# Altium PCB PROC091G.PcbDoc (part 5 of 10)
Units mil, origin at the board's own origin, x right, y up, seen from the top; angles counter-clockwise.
Board outline 4538.11 x 994.94 mil, 8 copper layers (Top Layer, GND1, Sig1, PWR1, PWR2, Sig2, GND2, Bottom Layer), stack 59.155 mil thick; 446 components, 329 nets, 5050 pads, 868 vias.
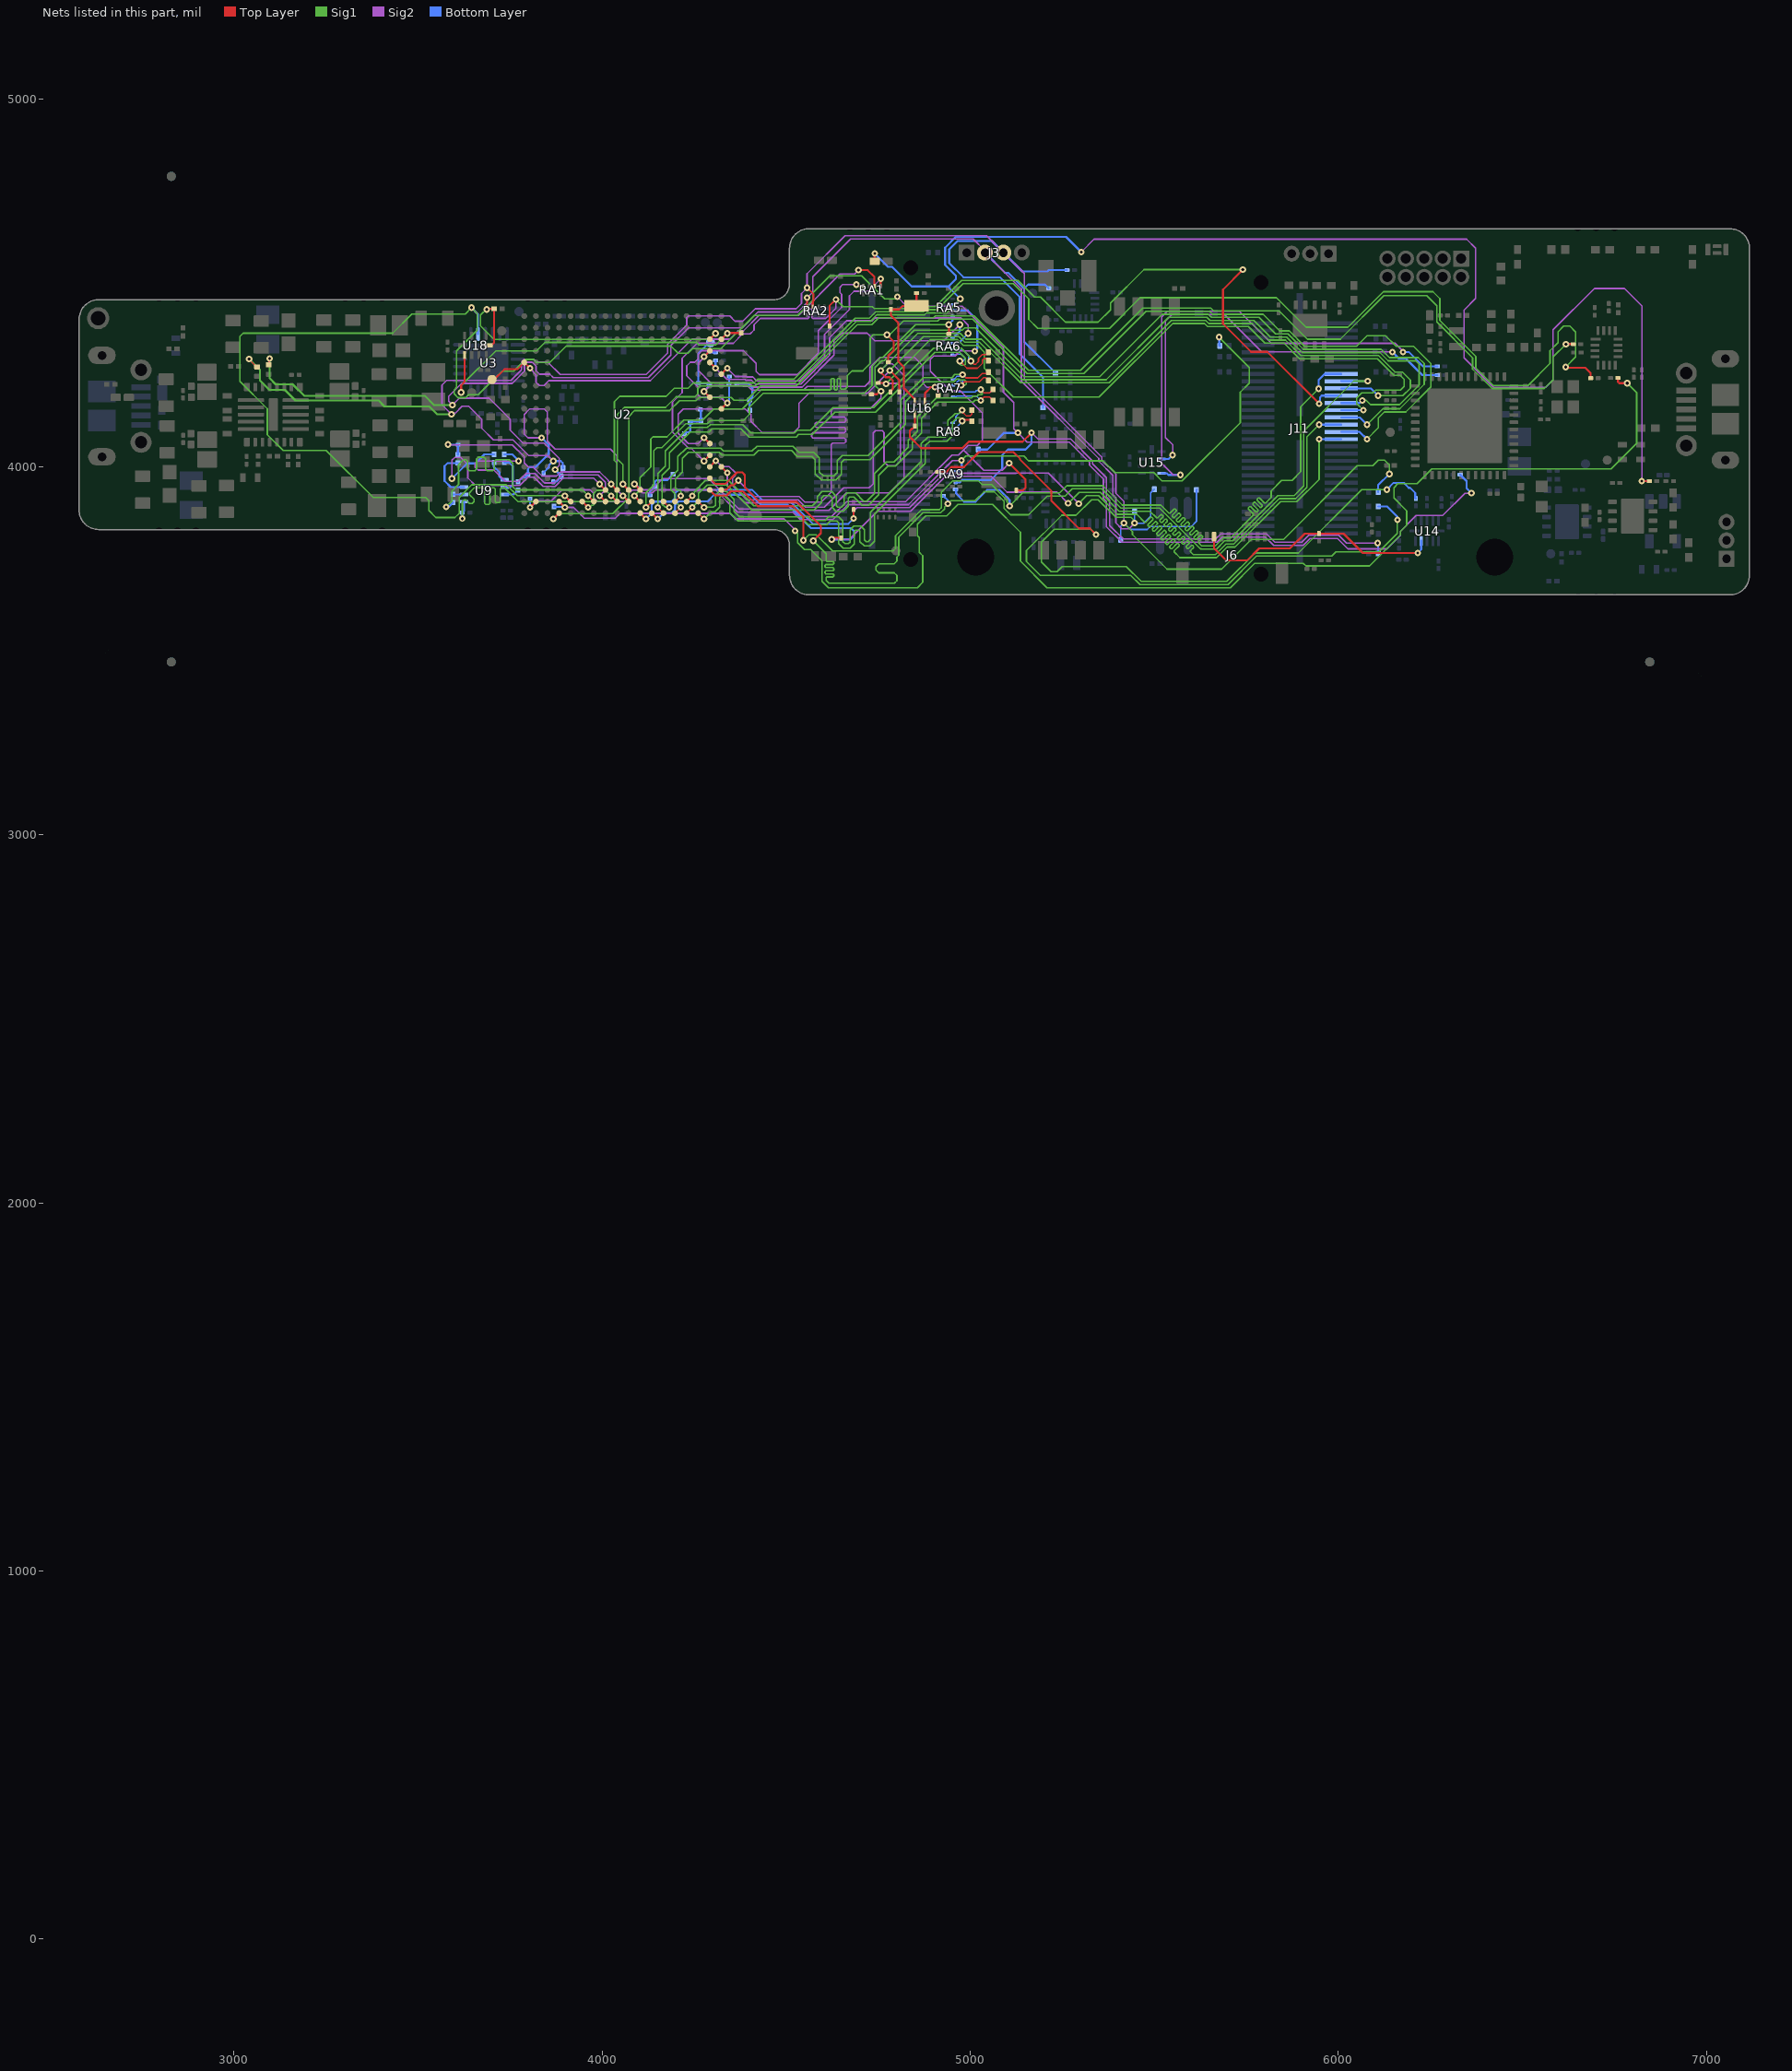
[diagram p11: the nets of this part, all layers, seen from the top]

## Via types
v1: diameter 18, hole 8, Top Layer to Bottom Layer, tented both sides, 832 vias
v2: diameter 19.68, hole 7.87, Top Layer to Bottom Layer, tented both sides, 34 vias
v3: diameter 17, hole 7.87, Top Layer to Bottom Layer, tented both sides, 1 vias
v4: diameter 17, hole 8, Top Layer to Bottom Layer, tented both sides, 1 vias

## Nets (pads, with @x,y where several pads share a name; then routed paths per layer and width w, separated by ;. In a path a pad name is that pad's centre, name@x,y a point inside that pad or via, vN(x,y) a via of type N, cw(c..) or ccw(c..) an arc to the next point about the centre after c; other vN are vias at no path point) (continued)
AR_CS1_LCD: R76.2 R106.2 | length 1971.8
  Top Layer w5.5: R106.2@4912.37,3985.56 4935.15,3985.56 4948.84,3999.25 4983.35,3999.25 5023.93,4039.83 5117.4,4039.83 5135.68,4021.55 5135.68,4019.4 5220.75,3934.33 5220.75,3907 5295.27,3832.48 5325.11,3832.48 v1(5341.82,3815.77)
  Sig1 w4.2: v1(5341.82,3815.77) 5327.56,3830.03 5228.54,3830.03 5193.48,3794.98 5193.48,3741.37 5219.62,3715.24 5236.36,3715.24 5250.14,3729.01 5423.81,3729.01 5464.6,3688.21 5696.86,3688.21 5774.21,3765.56 5891.75,3765.56 6064.18,3938 v1(6132,3938)
  Bottom Layer w5.5: v1(6132,3938) 6150.21,3956.21 6178.19,3956.21 6191.57,3942.84 6194.98,3942.84 6209.15,3928.68 6209.15,3915.09 R76.2@6210.78,3913.46
AR_CS1_LCD_T: J6.3 R183.1 U14.4 | length 688.3
  Top Layer w5.5: J6.3@5662.69,3810.06 5662.69,3778.74 5696.19,3745.25 5752.29,3745.25 5785.06,3778.01 5868.52,3778.01 5908.94,3818.43 R183.1@5947.68,3818.43 6014.38,3818.43 6067,3765.81 v1(6215.84,3765.81)
  Bottom Layer w5.5: v1(6215.84,3765.81) 6225.29,3775.26 U14.4@6225.29,3797.8 U14.4@6225.29,3799.77
AR_DMM_CLK: J11.15 R11.1 U2.U3 | length 2987.9
  Top Layer w5.5: U2.U3@4292.7,3936.89 4307.32,3922.26 4338.99,3922.26 4350.2,3933.47 4382.53,3933.47 4423.2,3892.8 4518.93,3892.8 4546.57,3865.15 v1(4546.57,3799.81)
  Sig1 w4.2: v1(4546.57,3799.81) 4562.05,3815.29 4582.04,3815.29 4626.12,3771.22 4790.64,3771.22 4797.35,3777.92 4797.35,3812.59 4868.02,3883.26 4916.38,3883.26 4922.15,3889.03 4922.15,3931.08 4952.52,3961.45 5022.73,3961.45 5032.58,3951.6 5057.93,3951.6 5100.15,3909.38 5100.15,3904.15 5107.05,3897.25 v1(5107.05,3893.52) 5142.43,3928.9 5242.97,3928.9 5262.41,3948.34 5360.74,3948.34 5413.2,3895.88 5518.19,3895.88 5539.96,3874.11 5542.93,3874.11 5553.82,3885 5556.79,3885 5559.76,3882.03 5559.76,3879.06 5548.87,3868.17 5548.87,3865.2 5551.84,3862.23 5554.81,3862.23 5565.7,3873.12 5568.67,3873.12 5571.64,3870.15 5571.64,3867.18 5560.75,3856.29 5560.75,3853.32 5563.72,3850.35 5566.69,3850.35 5577.58,3861.24 5580.55,3861.24 5583.52,3858.27 5583.52,3855.3 5572.62,3844.41 5572.62,3841.44 5575.59,3838.47 5578.56,3838.47 5589.46,3849.37 5592.43,3849.37 5595.4,3846.4 5595.4,3843.43 5584.5,3832.53 5584.5,3829.56 5587.47,3826.59 5590.44,3826.59 5601.34,3837.49 5604.31,3837.49 5607.27,3834.52 5607.27,3831.55 5596.38,3820.65 5596.38,3817.69 5599.35,3814.72 5602.32,3814.72 5613.21,3825.61 5616.18,3825.61 5619.15,3822.64 5619.15,3819.67 5608.26,3808.78 5608.26,3805.81 5611.23,3802.84 5614.2,3802.84 5625.2,3813.84 5628.17,3813.84 5631.14,3810.87 5631.14,3807.9 5620.14,3796.9 5620.14,3793.93 5628.77,3785.3 5666.23,3785.3 5687.95,3807.02 5708.3,3807.02 5769.88,3868.6 5769.88,3871.57 5756.13,3885.32 5756.13,3888.29 5759.1,3891.26 5762.07,3891.26 5775.82,3877.51 5778.79,3877.51 5781.76,3880.48 5781.76,3883.45 5768.01,3897.2 5768.01,3900.17 5770.98,3903.14 5773.95,3903.14 5787.7,3889.39 5790.67,3889.39 5793.64,3892.36 5793.64,3895.33 5779.89,3909.08 5779.89,3912.05 5782.86,3915.02 5785.83,3915.02 5799.58,3901.27 5802.55,3901.27 5817.91,3916.63 5817.91,3934.39 5846.28,3962.76 5874.33,3962.76 5897.85,3986.27 5897.85,4163.26 v1(5946.67,4212.08)
  Bottom Layer w5.5: R11.1@4960.02,3937.94 4961.69,3937.94 4961.69,3926.94 4983.21,3905.42 5014.32,3905.42 5045.7,3936.8 5080.2,3936.8 5107.05,3909.95 v1(5107.05,3893.52) ; v1(5946.67,4212.08) 5946.67,4235.89 5962.91,4252.14 J11.15@6007.91,4252.14
AR_DMM_SYNC: J11.17 R10.1 U2.U4 | length 2944.6
  Top Layer w5.5: U2.U4@4292.7,3968.38 4307.32,3953.76 4335.57,3953.76 4366.31,3984.5 4380.6,3984.5 4388,3977.1 4388,3944.27 4427.07,3905.2 4528.29,3905.2 4594.49,3839 4594.49,3819.69 v1(4573.55,3798.74)
  Sig1 w4.2: v1(4573.55,3798.74) 4608.7,3763.59 4608.7,3745.54 4611.65,3742.59 4627.33,3742.59 4629.43,3740.49 4629.43,3736.29 4627.33,3734.19 4607.72,3734.19 4605.62,3732.09 4605.62,3727.89 4607.72,3725.79 4627.33,3725.79 4629.43,3723.69 4629.43,3719.49 4627.33,3717.39 4607.72,3717.39 4605.62,3715.29 4605.62,3711.09 4607.72,3708.99 4627.33,3708.99 4629.43,3706.89 4629.43,3702.69 4627.33,3700.59 4610.8,3700.59 4608.7,3698.49 4608.7,3690.96 4616.3,3683.36 4793.88,3683.36 4800.87,3690.35 4800.87,3704.68 4793.61,3711.94 4751.42,3711.94 4744.16,3719.2 4744.16,3728.88 4751.42,3736.14 4793.61,3736.14 4800.87,3743.4 4800.87,3754.27 4806.18,3759.58 4806.18,3808.91 4872.14,3874.86 4919.86,3874.86 4930.55,3885.55 4930.55,3890.83 v1(4939.38,3899.66) 4947.59,3907.87 5013.3,3907.87 5037.73,3932.3 5065.35,3932.3 5091.75,3905.9 5091.75,3887.18 5109.3,3869.63 5158.29,3869.63 5209.16,3920.5 5258.24,3920.5 5277.67,3939.94 5357.26,3939.94 5409.72,3887.48 5514.71,3887.48 5625.29,3776.9 5627.71,3776.9 5627.97,3776.64 5669.45,3776.64 5691.43,3798.62 5712.88,3798.62 5836.14,3921.88 5880.54,3921.88 5906.25,3947.58 5906.25,4096.8 6041.9,4232.45 v1(6080,4232.45)
  Bottom Layer w5.5: R10.1@4927.02,3921 4939.38,3908.65 v1(4939.38,3899.66) ; J11.17@6007.91,4232.45 v1(6080,4232.45)
AR_DP0: J11.19 R88.1 U2.U7 | length 2828.1
  Top Layer w5.5: v1(4276.95,4078.62) U2.U7@4292.7,4062.87 ; v1(4781.5,4261.73) 4807.4,4235.84 R88.1@4807.4,4202.68
  Sig1 w4.2: v1(4781.5,4261.73) 4873.42,4353.65 4969.55,4353.65 4984.88,4338.32 5025.32,4338.32 5047.08,4316.55 5048.98,4316.55 5137.45,4228.08 5377.24,4228.08 5546.66,4397.5 5639.88,4397.5 5648.28,4389.1 5766.35,4389.1 5811.43,4344.02 5856.43,4344.02 5898.4,4302.05 6109.66,4302.05 6154.56,4257.15 6174.68,4257.15 6195.7,4236.13 6195.7,4213.63 6175.16,4193.08 v1(6108.22,4193.08)
  Sig2 w4.2: v1(4276.95,4078.62) 4261.23,4062.89 4234.4,4062.89 4207.08,4090.21 4207.08,4100.94 4207.08,4111.59 4207.08,4143.33 4220.78,4157.04 4389.09,4157.04 4404.46,4141.67 4404.46,4123.28 4435.52,4092.22 4519.97,4092.22 4535.14,4107.38 4535.14,4172.74 4551.69,4189.3 4551.95,4189.3 4562.68,4200.02 4721.12,4200.02 4781.5,4260.41 v1(4781.5,4261.73)
  Bottom Layer w5.5: J11.19@6007.91,4212.77 6088.54,4212.77 v1(6108.22,4193.08)
AR_DP1: J11.21 R130.1 U2.U6 | length 2845.6
  Top Layer w5.5: v1(4276.95,4015.63) U2.U6@4292.7,4031.37 ; R130.1@4617.95,4383.18 4617.95,4437 v1(4635.35,4454.4) ; v1(5740.89,4535.5) 5686.83,4481.44 5686.83,4388.68 5763.36,4312.14 5807.32,4312.14 v1(5947.91,4171.55)
  Sig1 w4.2: v1(4635.35,4454.4) 4654.9,4434.85 4734.43,4434.85 4739.59,4429.68 4869.35,4429.68 4874.57,4434.9 4905.63,4434.9 4976.85,4506.11 5130.05,4506.11 5175.09,4461.08 5190.85,4461.08 5259.06,4392.87 5347.95,4392.87 5381.12,4426.03 5381.12,4444.55 5472.07,4535.5 v1(5740.89,4535.5)
  Sig2 w4.2: v1(4276.95,4015.63) 4242.74,4049.83 4235.58,4049.83 4191.3,4094.11 4191.3,4175.11 4217.54,4201.35 4217.54,4294.54 4258.38,4335.38 4356.56,4335.38 4381.77,4360.58 4401.98,4360.58 4412.98,4371.58 4412.98,4386.05 4429.85,4402.91 4559.66,4402.91 4561.76,4405.01 4561.76,4426.8 4563.86,4428.9 4568.06,4428.9 4570.16,4426.8 4570.16,4405.01 4572.26,4402.91 4607.78,4402.91 4635.35,4430.49 v1(4635.35,4454.4)
  Bottom Layer w5.5: v1(5947.91,4171.55) 5950.3,4173.94 5950.3,4188.41 5954.98,4193.08 J11.21@6007.91,4193.08
AR_DP2: J11.23 R132.1 U2.V5 | length 3022.7
  Top Layer w5.5: U2.V5@4324.64,3999.43 v1(4340.39,3983.68) ; v1@4753.17,4260.24 4769.99,4243.43 4780.58,4243.43 4789.41,4234.6 4789.41,4210.12 R132.1@4786.18,4206.9 ; R132.1@4783.74,4202.68 4783.74,4204.48 R132.1@4786.16,4206.9
  Sig1 w4.2: v1(4757.17,4261.73) 4857.49,4362.05 4973.03,4362.05 4988.36,4346.72 5030.69,4346.72 5140.93,4236.48 5369.51,4236.48 5538.93,4405.9 5643.36,4405.9 5651.76,4397.5 5771.07,4397.5 5816.15,4352.42 5859.91,4352.42 5901.88,4310.45 6113.14,4310.45 6135.84,4287.75 6210.6,4287.75 6219.8,4278.55 6219.8,4222.21 6166.19,4168.6 6087.55,4168.6 6075.8,4180.35 v1(6065.27,4180.35)
  Sig2 w4.2: v1(4340.39,3983.68) 4340.39,3948.49 4386.9,3901.99 4528.64,3901.99 4548.94,3881.69 4616.75,3881.69 4663.78,3928.72 4780.31,3928.72 4820.7,3969.11 4820.7,4247.47 4788.5,4279.66 4775.1,4279.66 v1(4757.17,4261.73)
  Bottom Layer w5.5: J11.23@6007.91,4173.4 6058.32,4173.4 v1(6065.27,4180.35)
AR_DP3: J11.25 R133.1 U2.U5 | length 3084.4
  Top Layer w5.5: U2.U5@4293.15,4000.33 v1(4308.9,4016.07) ; R133.1@4750.69,4227.63 v1@4770.1,4227.63
  Sig1 w4.2: v1(4771.66,4225.41) 4891.49,4345.25 4966.07,4345.25 4981.4,4329.92 5020.4,4329.92 5038.68,4311.64 5038.68,4267.65 5116.96,4189.38 5350.41,4189.38 5550.14,4389.1 5636.4,4389.1 5644.8,4380.7 5755.73,4380.7 5800.81,4335.62 5852.95,4335.62 5894.92,4293.65 6106.18,4293.65 6151.51,4248.33 6168.51,4248.33 6179.13,4237.7 6179.13,4218.59 6168.92,4208.38 6101.88,4208.38 6093.85,4200.35 6063.63,4200.35 6049.97,4186.69 6049.97,4171.74 v1(6068,4153.71)
  Sig2 w4.2: v1(4308.9,4016.07) 4310.02,4016.07 4325.77,4000.33 4345.39,4000.33 4362,3983.71 4362,3976.46 4354.7,3969.16 4354.7,3949.12 4393.43,3910.39 4532.11,3910.39 4552.41,3890.09 4604.14,3890.09 4656.72,3942.67 4725.5,3942.67 4736.28,3953.45 4736.28,4091.85 4742.4,4097.98 4761.3,4097.98 4766.06,4093.22 4766.06,4013.57 4777.02,4002.6 4797.87,4002.6 4810.15,4014.88 4810.15,4218.01 4801.88,4226.27 4772.51,4226.27 v1(4771.66,4225.41)
  Bottom Layer w5.5: J11.25@6007.91,4153.71 v1(6068,4153.71)
AR_DP4: J11.27 R135.1 U2.V3 | length 3286.4
  Top Layer w5.5: U2.V3@4324.2,3936.89 4337.35,3936.89 4350.32,3949.86 4357.03,3949.86 v1(4370,3962.82) ; R135.1@4732.07,4196.8 4746.56,4196.8 v1@4752.8,4203.05
  Sig1 w4.2: v1(4757.82,4205.05) 4741.84,4221.04 4741.84,4269.89 4760.64,4288.69 4766.25,4288.69 4848.26,4370.7 4978.34,4370.7 4984.96,4377.32 5014.19,4377.32 5146.63,4244.88 5351.99,4244.88 5521.41,4414.3 5646.84,4414.3 5655.24,4405.9 5784.17,4405.9 5829.25,4360.82 5863.39,4360.82 5905.36,4318.85 6116.62,4318.85 6138.95,4296.52 6217.35,4296.52 6233.37,4280.5 6233.37,4223.91 6166.88,4157.42 6121.07,4157.42 v1(6078,4114.34)
  Sig2 w4.2: v1(4370,3962.82) 4414.04,3918.79 4535.59,3918.79 4550.54,3903.84 4595.78,3903.84 4622.63,3930.69 4622.63,4029.66 4622.63,4060.28 4626.18,4063.83 4658.3,4063.83 4661.85,4067.38 4661.85,4074.48 4658.3,4078.03 4622.63,4078.03 4572.87,4078.03 4569.32,4081.58 4569.32,4088.68 4572.87,4092.23 4622.63,4092.23 4658.15,4092.23 4661.7,4095.78 4661.7,4102.88 4658.15,4106.43 4622.63,4106.43 4582.47,4106.43 4578.92,4109.98 4578.92,4117.08 4582.47,4120.63 4622.63,4120.63 4658.3,4120.63 4661.85,4124.18 4661.85,4131.28 4658.3,4134.83 4626.18,4134.83 4622.63,4138.38 4622.63,4141.93 4622.63,4154.35 4623.63,4154.35 4627.18,4157.89 4729.11,4157.89 4757.82,4186.61 v1(4757.82,4205.05)
  Bottom Layer w5.5: J11.27@6007.91,4134.03 6058.32,4134.03 v1(6078,4114.34)
AR_DP5: J11.29 R137.1 U2.M1 | length 2745.3
  Top Layer w4.2: v1(4623.77,3802.58) 4628,3806.81 R137.1@4649.26,3806.81
  Top Layer w5.5: U2.M1@4135.22,3873.89 v1(4150.97,3858.15)
  Sig1 w4.2: v1(5266.1,3900.55) 5266.35,3900.55 5295.95,3930.16 5353.51,3930.16 5404.59,3879.08 5488.6,3879.08 5506.59,3861.08 5509.56,3861.08 5517.91,3869.43 5520.88,3869.43 5523.85,3866.46 5523.85,3863.49 5515.5,3855.14 5515.5,3852.17 5518.47,3849.2 5521.44,3849.2 5529.79,3857.55 5532.76,3857.55 5535.73,3854.58 5535.73,3851.61 5527.38,3843.26 5527.38,3840.29 5530.35,3837.32 5533.32,3837.32 5541.67,3845.67 5544.64,3845.67 5547.61,3842.7 5547.61,3839.73 5539.26,3831.38 5539.26,3828.41 5542.23,3825.44 5545.2,3825.44 5553.55,3833.79 5556.52,3833.79 5559.49,3830.82 5559.49,3827.85 5551.14,3819.5 5551.14,3816.53 5554.11,3813.56 5557.08,3813.56 5565.43,3821.91 5568.4,3821.91 5571.37,3818.94 5571.37,3815.97 5563.02,3807.62 5563.02,3804.65 5565.99,3801.68 5568.96,3801.68 5577.31,3810.03 5580.28,3810.03 5583.25,3807.06 5583.25,3804.09 5574.9,3795.74 5574.9,3792.77 5577.87,3789.8 5580.84,3789.8 5589.19,3798.15 5592.16,3798.15 5595.13,3795.18 5595.13,3792.21 5586.78,3783.86 5586.78,3780.89 5589.75,3777.92 5592.72,3777.92 5601.07,3786.27 5604.04,3786.27 5607.01,3783.3 5607.01,3780.33 5598.66,3771.98 5598.66,3769.01 5606.08,3761.59 5666.28,3761.59 5694.9,3790.22 5716.36,3790.22 5839.62,3913.48 5884.02,3913.48 5914.65,3944.1 5914.65,4081.09 v1(5947.9,4114.34)
  Sig2 w4.2: v1(4623.77,3802.58) 4671.15,3802.58 4747.86,3879.29 4838.19,3879.29 4932.8,3973.9 5057.14,3973.9 5100.13,3930.91 5235.75,3930.91 v1(5266.1,3900.55)
  Bottom Layer w5.5: v1(4150.97,3858.15) 4166.72,3873.9 4176.3,3873.9 4176.39,3873.99 4188.95,3873.99 4198.11,3883.16 4198.11,3895.93 4207.67,3905.49 4286.39,3905.49 4304.8,3923.9 4404.12,3923.9 4431.61,3896.41 4504.41,3896.41 4567.49,3833.32 4676.35,3833.32 4684.37,3825.3 4684.37,3812.31 4674.64,3802.58 v1(4623.77,3802.58) ; v1@5949.4,4114.34 J11.29@6007.91,4114.34
AR_DP6: J11.31 R138.1 U2.L2 | length 3310.6
  Top Layer w5.5: v1(4087.98,3921.14) U2.L2@4103.72,3905.39 ; v1(4774.14,4358.34) 4792.59,4339.89 4792.59,4316.78 4777.4,4301.59 R138.1@4777.4,4284.46
  Sig1 w4.2: v1(4087.98,3921.14) 4103.28,3936.44 4103.28,3970.27 4132.4,3999.39 4132.4,4075.87 4137.74,4081.21 4176.39,4081.21 4222.19,4127.01 4273.2,4127.01 4303.1,4156.91 4380.91,4156.91 4432.76,4208.76 4620.09,4208.76 4622.19,4210.86 4622.19,4237.62 4624.29,4239.72 4628.49,4239.72 4630.59,4237.62 4630.59,4210.86 4632.69,4208.76 4636.89,4208.76 4638.99,4210.86 4638.99,4237.62 4641.09,4239.72 4645.29,4239.72 4647.39,4237.62 4647.39,4212.96 4649.49,4210.86 4659.99,4210.86 4666.18,4217.05 4666.18,4247.54 4678.82,4260.18 4708.15,4260.18 4728.57,4280.6 4728.57,4350.04 4736.87,4358.34 v1(4774.14,4358.34) 4780.99,4358.34 4818.73,4396.08 4911.67,4396.08 4916.89,4401.3 5006.98,4401.3 5155.01,4253.28 5308.42,4253.28 5477.85,4422.7 5650.32,4422.7 5658.72,4414.3 5795.45,4414.3 5840.53,4369.22 5866.87,4369.22 5908.84,4327.25 6049.4,4327.25 6078.2,4356.05 6128.4,4356.05 6157.32,4327.12 6204.71,4327.12 6251.72,4280.11 6251.72,4216.88 6183.52,4148.69 6125.47,4148.69 6109.11,4132.33 6109.11,4106.08 v1(6078,4074.97)
  Bottom Layer w5.5: J11.31@6007.91,4094.66 6058.32,4094.66 v1(6078,4074.97)
AR_DP7: J11.33 R140.1 U2.L1 | length 2695.9
  Top Layer w5.5: U2.L1@4103.72,3873.89 v1(4119.47,3858.15) ; v1(4683.56,3859.2) R140.1@4683.56,3883.42
  Sig1 w4.2: v1(5294.79,3899.93) 5294.79,3900.21 5316.28,3921.7 5348.48,3921.7 5399.51,3870.68 5452.39,3870.68 5474.16,3848.91 5477.13,3848.91 5490.49,3862.28 5493.46,3862.28 5496.43,3859.31 5496.43,3856.34 5483.07,3842.97 5483.07,3840 5486.04,3837.03 5489.01,3837.03 5502.53,3850.55 5505.5,3850.55 5508.47,3847.59 5508.47,3844.62 5494.94,3831.09 5494.94,3828.12 5497.91,3825.15 5500.88,3825.15 5514.41,3838.68 5517.38,3838.68 5520.35,3835.71 5520.35,3832.74 5506.82,3819.21 5506.82,3816.24 5509.79,3813.27 5512.76,3813.27 5526.29,3826.8 5529.26,3826.8 5532.23,3823.83 5532.23,3820.86 5518.7,3807.33 5518.7,3804.36 5521.67,3801.39 5524.64,3801.39 5538.17,3814.92 5541.14,3814.92 5544.11,3811.95 5544.11,3808.98 5530.58,3795.45 5530.58,3792.48 5533.55,3789.52 5536.52,3789.52 5550.05,3803.04 5553.01,3803.04 5555.98,3800.07 5555.98,3797.1 5542.46,3783.58 5542.46,3780.61 5545.43,3777.64 5548.4,3777.64 5561.92,3791.16 5564.89,3791.16 5567.86,3788.19 5567.86,3785.22 5554.34,3771.7 5554.34,3768.73 5569.88,3753.19 5669.76,3753.19 5698.38,3781.82 5719.84,3781.82 5843.1,3905.08 5887.5,3905.08 5947.9,3965.47 v1(5947.9,4074.97)
  Sig2 w4.2: v1(4683.56,3859.2) 4683.56,3879.44 4692.92,3888.81 4835.83,3888.81 4929.32,3982.3 5124.56,3982.3 5124.84,3982.58 5212.14,3982.58 v1(5294.79,3899.93)
  Bottom Layer w5.5: v1(4119.47,3858.15) 4135.23,3873.9 4135.23,3896.22 4144.4,3905.39 4188.85,3905.39 4198.31,3914.85 4198.31,3927.62 4207.48,3936.79 4408.21,3936.79 4437.09,3907.91 4509.17,3907.91 4572.26,3844.82 4669.18,3844.82 v1(4683.56,3859.2) ; v1@5949.4,4074.97 J11.33@6007.91,4074.97
AR_GPIO_0: R66.1 RA5.8 U2.M2 | length 1223.3
  Top Layer w5.5: v1(4119.47,3889.64) U2.M2@4135.22,3905.39 ; v1(4942,4386) 4942.18,4385.82 4942.18,4361.16 R66.1@4942.37,4360.97
  Sig1 w4.2: v1(4119.47,3889.64) 4119.47,3928.77 4140.8,3950.1 4140.8,4043.53 4149.28,4052.01 4162.53,4052.01 4171.08,4060.56 4171.08,4060.77 4227.45,4117.14 4285.44,4117.14 4294.17,4125.86 4384.06,4125.86 4400.5,4142.3 4400.5,4162.2 4437.86,4199.56 4712.32,4199.56 4733.44,4220.68 4733.44,4273.37 4757.16,4297.09 4762.77,4297.09 4851.68,4386 v1(4942,4386)
  Bottom Layer w5.5: v1(4942,4386) 4942,4387.38 4952,4397.38 4952,4408.75 RA5.8@4952.34,4409.09
AR_GPIO_1: R129.2 RA5.7 U2.L3 | length 1973.2
  Top Layer w5.5: v1(4087.98,3952.63) U2.L3@4103.72,3936.89 ; v1(5105.98,4009.88) 5150.25,3965.61 5150.25,3942.67 5143.53,3935.94 R129.2@5125.2,3935.94
  Sig2 w4.2: v1(4087.98,3952.63) 4091.71,3952.63 4099.51,3944.84 4105.63,3944.84 4113.14,3937.33 4133.62,3937.33 4164.22,3967.93 4288.79,3967.93 4371.53,3885.19 4521.68,3885.19 4541.98,3864.89 4623.71,3864.89 4664.43,3905.61 4824.97,3905.61 4950.66,4031.3 4967.81,4031.3 4982.07,4045.57 ; v1(5012.86,4314.37) 4972.55,4314.37 4959.4,4301.21 4901.37,4301.21 4891.85,4291.7 4891.85,4259.83 4945.46,4206.23 4973.37,4206.23 5033.41,4146.19 5033.41,4072.27 5019.42,4058.27 4994.78,4058.27 4982.07,4045.57 ; v1(5105.98,4009.88) 5086.81,3990.7 5036.94,3990.7 4982.07,4045.57
  Bottom Layer w5.5: RA5.7@4952.34,4424.84 4993.16,4424.84 5019.72,4398.28 5019.72,4321.23 v1(5012.86,4314.37)
AR_GPIO_2: LD3.1 R115.1 RA5.6 U2.K3 | length 4777.5
  Top Layer w4.2: v1(6824.78,3961) R115.1@6844.78,3961
  Top Layer w5.5: v1(4056.48,3952.63) U2.K3@4072.23,3936.89 ; LD3.1@4740.42,4558.15 4740.42,4579.31 v1(4740.56,4579.45)
  Sig1 w4.2: v1(4056.48,3952.63) 4056.48,4005.96 4041.88,4020.56 4041.88,4142.66 4060.53,4161.31 4172.41,4161.31 4201.11,4190 4251.5,4190 4260.06,4198.55 4260.06,4212.83 4266.43,4219.2 4416.2,4219.2 4425.61,4228.61 4524.36,4228.61 4690.64,4394.88 4728.84,4394.88 4746.84,4412.88 4876.31,4412.88 4881.53,4418.1 4935.25,4418.1 v1(4973.31,4456.16)
  Sig2 w4.2: v1(5301.7,4583.36) 5336.66,4618.32 6348.76,4618.32 6373.39,4593.69 6373.39,4457.12 6341.62,4425.36 6341.62,4296 6350.18,4287.44 6350.52,4287.44 6359.48,4278.48 6359.48,4278.14 6421.96,4215.66 6563.1,4215.66 6583.51,4236.08 6583.51,4372.08 6695.72,4484.29 6777.2,4484.29 6824.78,4436.7 v1(6824.78,3961)
  Bottom Layer w5.5: v1(4740.56,4579.45) 4776.96,4543.06 4787.7,4543.06 4841.01,4489.75 4939.73,4489.75 ; RA5.6@4952.34,4440.59 4957.74,4440.59 v1(4973.31,4456.16) 4939.73,4489.75 ; v1(5301.7,4583.36) 5260.4,4624.66 4960.97,4624.66 4931.76,4595.44 4931.76,4548.27 4961.18,4518.86 4961.18,4509.82 4941.1,4489.75 4939.73,4489.75
AR_HOSTINTR1: R3.1 R152.1 RA9.6 U2.B2 | length 2584
  Top Layer w5.5: v1(3804.51,3889.64) U2.B2@3820.26,3905.39
  Sig1 w4.2: v1(4976,4017) 4988.02,4029.02 5145.79,4029.02 5158.6,4016.22 5253.02,4016.22 5361.38,4016.22 5393.69,3983.92 5448.46,3983.92 5448.61,3983.77 5498.68,3983.77 5521.19,3961.26 5575.69,3961.26 5733.69,4119.26 5733.69,4202.55 5758.37,4227.23 5758.37,4269.94 v1(5675.9,4352.4)
  Sig2 w4.2: v1(3804.51,3889.64) 3806.53,3889.64 3824.85,3907.96 3862.94,3907.96 3892.18,3937.2 3967.57,3937.2 3977.29,3927.47 3977.29,3915.77 3978.19,3914.88 3978.19,3914.8 3988.05,3904.94 4061.92,3904.94 4072.68,3915.7 4072.68,3927.47 4081.64,3936.44 4102.15,3936.44 4109.66,3928.93 4137.13,3928.93 4145.53,3937.33 4307.51,3937.33 4368.05,3876.79 4518.2,3876.79 4538.5,3856.49 4627.18,3856.49 4667.91,3897.21 4832.35,3897.21 4952.14,4017 v1(4976,4017)
  Bottom Layer w5.5: R3.1@3804.15,3912.76 3804.15,3890 v1(3804.51,3889.64) ; RA9.6@4960.68,3987.64 4969.78,3987.64 4977,3994.85 4977,4016 v1(4976,4017) ; v1(5675.9,4352.4) 5676.88,4351.43 5676.88,4329.65 R152.1@5678.13,4328.4
AR_LVDS_0_N: R149.1 RA6.7 U2.N1 | length 1305.1
  Top Layer w4: v1(4150.97,3889.64) U2.N1@4166.72,3873.89 ; v1(5001.79,4287.19) 5010.21,4278.77 5015.39,4278.77 5022.74,4286.12 5022.74,4294.77 5032.99,4305.03 5043.31,4305.03 R149.1@5049.31,4311.03
  Sig1 w3.5: v1(4150.97,3889.64) 4151.55,3890.22 4151.55,3981.11 4171.69,4001.25 4171.69,4042.71 4235.17,4106.2 4286.1,4106.2 4294.1,4114.2 4382.36,4114.2 4404.66,4091.9 4522.5,4091.9 4529.55,4098.95 4566.09,4098.95 4627.29,4160.15 4738.33,4160.15 4900.05,4321.87 4975.88,4321.87 ; 4975.89,4321.88 4998.34,4299.42 4998.34,4290.64 v1(5001.79,4287.19)
  Bottom Layer w4: RA6.7@4951.92,4319.52 4959.91,4319.52 4962.29,4317.15 4979.99,4317.15 4995.79,4301.35 4995.79,4293.19 v1(5001.79,4287.19)
AR_LVDS_0_P: R148.1 RA6.8 U2.N2 | length 1338.8
  Top Layer w4: U2.N2@4166.72,3905.39 v1(4182.46,3889.64) ; v1(4971.79,4287.19) 4991.21,4267.77 5019.95,4267.77 5033.74,4281.57 5033.74,4290.22 5037.55,4294.03 5043.31,4294.03 R148.1@5049.31,4288.03
  Sig1 w3.5: v1(4182.46,3889.64) 4171.27,3889.64 4163.08,3897.83 4163.08,3976.39 4183.19,3996.49 4183.19,4037.94 4239.94,4094.7 4290.86,4094.7 4298.86,4102.7 4377.6,4102.7 4399.9,4080.4 4527.2,4080.4 4534.25,4087.45 4570.85,4087.45 4632.05,4148.65 4743.09,4148.65 4904.81,4310.37 4971.1,4310.37 ; 4971.12,4310.38 4986.84,4294.66 4986.84,4278.53 4984.08,4275.76 4975.65,4275.76 4971.79,4279.61 v1(4971.79,4287.19)
  Bottom Layer w4: RA6.8@4951.92,4303.77 4959.91,4303.77 4962.29,4306.15 4975.44,4306.15 4984.79,4296.79 4984.79,4290.54 4981.45,4287.19 v1(4971.79,4287.19)
AR_LVDS_1_N: R147.1 RA7.5 U2.P1 | length 1308.8
  Top Layer w4: U2.P1@4198.21,3873.89 v1(4213.96,3889.64) ; v1(4979.65,4250.36) 4988.57,4241.44 5020.56,4241.44 5032.55,4253.43 5046.25,4253.43 R147.1@5050.01,4257.19
  Sig1 w3.5: v1(4213.96,3889.64) 4198.21,3905.39 4198.21,3926.53 4187.47,3937.27 4187.47,3971.89 4206.2,3990.62 4206.2,4027.46 4229.08,4050.35 4322.62,4050.35 4330.06,4042.9 4407.6,4042.9 4420.41,4055.71 4519.06,4055.71 4535.16,4039.6 4575.38,4039.6 4590.61,4024.38 4590.61,3985.36 4600.71,3975.25 4630.15,3975.25 4638.51,3983.61 4638.51,4016.74 4652.59,4030.82 4723.05,4030.82 4812.2,4119.96 4812.2,4182.15 4872.61,4242.55 4950.52,4242.55 4958.25,4250.28 v1@4979.57,4250.28 ; v1@4973.38,4246.91 4976.2,4246.91 v1@4979.57,4250.28 ; v1@4979.65,4250.28 v1@4979.57,4250.28 ; v1(4979.65,4250.36) v1@4979.57,4250.28
  Bottom Layer w4: RA7.5@4953.34,4237.27 4955.58,4237.27 4963.67,4245.36 v1@4974.4,4245.36
AR_LVDS_1_P: R146.1 RA7.6 U2.P2 | length 1304.2
  Top Layer w4: U2.P2@4198.21,3905.39 v1(4213.96,3921.14) ; v1(4975.73,4221.53) 4984.64,4230.44 5025.11,4230.44 5037.11,4242.43 5041.77,4242.43 R146.1@5050.01,4234.19
  Sig1 w3.5: v1(4213.96,3921.14) 4213.96,3932.73 4210.37,3936.32 4204.69,3936.32 4198.97,3942.04 4198.97,3967.13 4217.7,3985.85 4217.7,4022.7 4233.85,4038.85 4317.85,4038.85 4325.3,4031.4 4412.36,4031.4 4425.17,4044.21 4514.29,4044.21 4530.4,4028.1 4570.62,4028.1 4579.11,4019.61 4579.11,3980.59 4595.95,3963.75 4634.92,3963.75 4650.01,3978.85 4650.01,4011.97 4657.35,4019.32 4727.82,4019.32 4823.7,4115.2 4823.7,4177.38 4877.37,4231.05 4955.29,4231.05 4963.01,4238.78 4970.01,4238.78 4973.38,4235.41 4984.3,4235.41 4989.18,4230.53 4989.18,4224.42 4986.29,4221.53 v1(4975.73,4221.53)
  Bottom Layer w4: RA7.6@4953.34,4221.53 4958.16,4221.53 4962.91,4226.27 4962.91,4228.23 4969.04,4234.36 4978.08,4234.36 4981.1,4231.35 v1@4981.1,4226.71
AR_LVDS_CLK_N: R145.1 RA7.7 U2.R2 | length 1272.5
  Top Layer w4: U2.R2@4229.71,3905.39 v1(4245.46,3921.14) ; v1(5028.6,4209.4) 5037.6,4200.4 5052.42,4200.4 5056.27,4204.25 5057.25,4204.25 5062.14,4209.14 R145.1@5062.14,4210.12
  Sig1 w3.5: v1(4245.46,3921.14) 4250.5,3926.18 4250.5,3932.09 4280.77,3962.36 4343.54,3962.36 4411.66,3894.25 4571.32,3894.25 4584.54,3907.46 4584.54,3919.41 4597.67,3932.55 4623.26,3932.55 4636.4,3919.42 4636.4,3894.34 4640.5,3890.23 4650.74,3890.23 4657.7,3897.19 4657.7,3919.66 4667,3928.97 4688.46,3928.97 4710.76,3906.67 4718.99,3906.67 4740.68,3928.37 4740.68,3981.58 4772.11,4013 4792.5,4013 4831.85,4052.35 4831.85,4071.18 4856.96,4096.29 4856.96,4134.41 4856.96,4136.18 4907.62,4186.84 5003.07,4186.84 5008.13,4191.9 5018.96,4191.9 5022.41,4195.35 5030.84,4195.35 5033.13,4197.64 5033.13,4204.87 v1(5028.6,4209.4)
  Bottom Layer w4: RA7.7@4953.34,4205.78 4961.34,4205.78 4963.72,4203.4 4992.27,4203.4 ; 4992.28,4203.4 5002.6,4203.4 5013.92,4203.4 5017.24,4206.72 5025.92,4206.72 v1(5028.6,4209.4)
AR_LVDS_CLK_P: R144.1 RA7.8 U2.R1 | length 1271.2
  Top Layer w4: U2.R1@4229.71,3873.89 v1(4245.46,3889.64) ; v1(5028.6,4180.4) 5037.6,4189.4 5052.87,4189.4 5056.27,4185.99 5057.25,4185.99 5062.14,4181.1 R144.1@5062.14,4180.12
  Sig1 w3.5: v1(4245.46,3889.64) 4262,3906.19 4262,3927.33 4285.53,3950.86 4338.78,3950.86 4406.89,3882.75 4576.09,3882.75 4596.04,3902.7 4596.04,3914.65 4602.44,3921.05 4618.5,3921.05 4624.9,3914.65 4624.9,3889.58 4635.74,3878.73 4655.5,3878.73 4669.2,3892.43 4669.2,3914.37 4672.29,3917.47 4683.7,3917.47 4705.99,3895.17 4723.75,3895.17 4752.18,3923.6 4752.18,3976.81 4776.87,4001.5 4797.26,4001.5 4843.35,4047.59 4843.35,4066.42 4868.46,4091.53 4868.46,4131.41 4912.38,4175.34 5007.84,4175.34 5012.9,4180.4 v1(5028.6,4180.4)
  Bottom Layer w4: RA7.8@4953.34,4190.03 4961.34,4190.03 4963.72,4192.4 4987.72,4192.4 4996.6,4192.4 5016.6,4192.4 v1(5028.6,4180.4)
AR_LVDS_FRCLK_N: R143.1 RA8.5 U2.T2 | length 1282.7
  Top Layer w4: U2.T2@4261.2,3905.39 v1(4276.95,3889.64) ; v1(4978.15,4153.91) 4978.15,4149.41 4988.99,4138.57 5000.39,4138.57 5004.28,4142.46 R143.1@5004.28,4153.69
  Sig1 w3.5: v1(4276.95,3889.64) 4302.37,3889.64 4307.79,3895.06 4307.79,3921.8 4318.23,3932.23 4337.81,3932.23 4358.82,3911.22 4358.82,3879.44 4373.94,3864.32 4559.76,3864.32 4570.08,3854 4605.74,3854 4615.24,3863.5 4642.93,3863.5 4654.4,3852.03 4654.4,3796.6 4660.23,3790.77 4668.84,3790.77 4673.44,3795.37 4673.44,3828.02 4684.1,3838.67 4703.01,3838.67 4712.34,3829.34 4712.34,3801.17 4717.6,3795.91 4722.41,3795.91 4729.13,3802.63 4729.13,3876.65 4866.74,4014.26 4866.74,4062.56 4885.24,4081.06 4931.87,4081.06 4939.98,4089.16 4939.98,4125.23 4959.7,4144.96 4969.2,4144.96 v1(4978.15,4153.91)
  Bottom Layer w4: RA8.5@4952.69,4119.49 4954.75,4119.49 4961.25,4126 4961.25,4137.01 v1(4978.15,4153.91)
AR_LVDS_FRCLK_P: R142.1 RA8.6 U2.T1 | length 1263.1
  Top Layer w4: U2.T1@4261.2,3873.89 v1(4276.95,3858.15) ; v1(4978.25,4124.51) 4978.25,4124.57 4981.25,4127.57 5000.41,4127.57 R142.1@5004.28,4123.69
  Sig1 w3.5: v1(4276.95,3858.15) 4296.95,3878.14 4307.14,3878.14 4319.29,3890.3 4319.29,3917.03 4322.99,3920.73 4333.04,3920.73 4347.32,3906.46 4347.32,3874.68 4369.18,3852.82 4550.24,3852.82 4560.56,3842.5 4610.5,3842.5 4620,3852 4638.16,3852 4642.9,3847.26 4642.9,3791.83 4655.47,3779.27 4673.6,3779.27 4684.94,3790.61 4684.94,3823.25 4688.86,3827.17 4698.24,3827.17 4700.84,3824.58 4700.84,3796.41 4712.84,3784.41 4727.18,3784.41 4740.63,3797.86 4740.63,3871.89 4878.24,4009.49 4878.24,4057.8 4890,4069.56 4936.64,4069.56 4951.48,4084.4 4951.48,4120.47 4964.47,4133.46 4972.45,4133.46 4978.25,4127.66 v1(4978.25,4124.51)
  Bottom Layer w4: RA8.6@4952.69,4103.74 4959.55,4103.74 4978.25,4122.44 v1(4978.25,4124.51)
AR_MCUCLKOUT: RA1.1 U2.V13 | length 645.6
  Top Layer w5.5: U2.V13@4324.2,4251.85 v1(4339.94,4267.59) ; RA1.1@4756.3,4490.32 RA1.1@4756.8,4490.32 4756.8,4509.89 v1(4757.37,4510.46)
  Sig2 w4.2: v1(4339.94,4267.59) 4362.44,4245.1 4391.75,4245.1 4393.12,4243.74 4409.56,4243.74 4420.13,4233.16 4536.42,4233.16 4604.57,4301.31 4604.57,4360.07 4672,4427.5 4672,4464.08 4684.7,4476.78 4723.69,4476.78 v1(4757.37,4510.46)
AR_MISO1: R121.2 U2.D1 | length 3605.8
  Top Layer w5.5: v1(3867.5,3858.15) U2.D1@3883.25,3873.89 ; v1@6621.04,4333.23 R121.2@6639.03,4333.23
  Sig1 w4.2: v1(3867.5,3858.15) 3882.1,3872.75 4029.45,3872.75 4072.59,3915.88 4072.59,4137.05 4087.94,4152.4 4183.51,4152.4 4210.87,4179.76 4255.19,4179.76 4263.84,4188.41 4350.62,4188.41 4358.63,4180.4 4391.83,4180.4 4431.01,4219.57 4527.21,4219.57 4693.5,4385.86 4732.86,4385.86 4751.48,4404.48 4900.45,4404.48 4905.67,4409.7 5010.46,4409.7 5158.48,4261.68 5299.73,4261.68 5469.15,4431.1 5653.8,4431.1 5661.4,4423.5 5798.33,4423.5 5798.56,4423.73 5811.23,4423.73 5811.46,4423.5 5838.95,4423.5 5915.77,4346.67 6005.71,4346.67 6123.87,4464.82 6240.01,4464.82 6267.56,4437.28 6267.56,4393.69 6365.11,4296.14 6365.11,4265.23 6417.8,4212.54 6559.97,4212.54 6583.51,4236.08 6583.51,4298.06 v1(6618.45,4333)
AR_MOSI1: R128.2 U2.F2 | length 3774.9
  Top Layer w5.5: U2.F2@3946.24,3905.39 v1(3961.99,3889.64) ; v1(6617.81,4271) 6619.56,4269.25 6670.56,4269.25 6685.71,4254.1 R128.2@6685.71,4240.71
  Sig1 w4.2: v1(3961.99,3889.64) 3965.73,3889.64 3971.33,3895.25 3974.95,3895.25 3985.79,3906.08 4031.07,3906.08 4040.28,3915.29 4040.28,4010.28 4033.48,4017.08 4033.48,4176.94 4047.75,4191.21 4173.98,4191.21 4196.34,4213.58 4233.79,4213.58 4248,4227.79 4412.91,4227.79 4422.6,4237.48 4521.36,4237.48 4687.78,4403.9 4725.9,4403.9 4743.28,4421.28 4872.83,4421.28 4878.05,4426.5 4909.11,4426.5 4980.33,4497.71 5117.3,4497.71 5158.98,4456.04 5158.98,4400.4 5183.31,4376.07 5378.55,4376.07 5461.64,4459.16 5831.89,4459.16 5912.1,4378.95 6026.12,4378.95 6122.68,4475.51 6257.37,4475.51 6275.96,4456.92 6275.96,4397.17 6373.51,4299.62 6373.51,4268.7 6421.28,4220.94 6515.39,4220.94 6575.11,4280.65 6575.11,4315.36 6596.98,4337.23 6596.98,4366.76 6612.22,4382 6629,4382 6645.16,4365.84 6645.16,4298.35 v1(6617.81,4271)
AR_MSS_LOGGER: R58.1 R131.1 U2.E2 U3.20 | length 6045.4
  Top Layer w5.5: v1(3899,3921.14) U2.E2@3914.75,3905.39
  Sig1 w4.2: v1(3899,3921.14) 3769.66,3921.14 3740,3950.8 3646.32,3950.8 3611.78,3916.26 3611.78,3873.46 3600.32,3861.99 3548.65,3861.99 3529.11,3881.54 3529.11,3908.04 3521.06,3916.08 3378.49,3916.08 3250.41,4044.17 3133.51,4044.17 3090.52,4087.16 3090.52,4157.48 3016.21,4231.78 3016.21,4353.98 3025.19,4362.95 3431.15,4362.95 3483.12,4414.91 3628.06,4414.91 v1(3645.27,4432.13) 3661.33,4416.07 3661.33,4370.68 3605.01,4314.36 3605.01,4215.83 3598.11,4208.93 3598.11,4198.04 3608.58,4187.57 3629.35,4187.57 3637.54,4195.75 3663.79,4195.75 3727.83,4259.8 3760.1,4259.8 3791.6,4291.29 3814.33,4291.29 3822.44,4283.18 3858,4283.18 3902.82,4328 4187.01,4328 4206.72,4308.29 4233.02,4308.29 4245.78,4321.05 4322.7,4321.05 4371.53,4369.88 4372,4369.88 4413.43,4411.31 4530.98,4411.31 4574.06,4454.4 4574.06,4473.83 4619.07,4518.84 4705.16,4518.84 4768,4456 4796.3,4456 v1(4802.08,4461.78)
  Sig2 w4.2: v1(4802.08,4461.78) 4827.52,4436.35 4978.93,4436.35 5090.04,4325.23 5090.04,4203.06 5118.76,4174.34 5118.76,4103.12 v1(5129.5,4092.38) 5155.06,4066.82 5269.45,4066.82 5324.25,4012.02 5324.25,4004.26 5362.07,3966.43 5362.07,3914 5370.47,3905.6 5370.47,3836.84 5412.32,3794.99 5670.75,3794.99 5684.93,3809.17 5801.61,3809.17 5824.27,3786.51 5904.79,3786.51 5923.31,3805.03 5998.1,3805.03 6026.05,3777.08 6132.68,3777.08 6168.85,3813.24 6168.85,3824.51 6211.7,3867.36 6283.41,3867.36 6344.05,3928 v1(6361.81,3928)
  Bottom Layer w5.5: v1(3645.27,4432.13) 3663.08,4414.32 U3.20@3663.12,4360.53 ; R58.1@5021.79,4046.94 5046.79,4046.94 5091.61,4091.76 5129.5,4091.76 v1(5129.5,4092.38) ; R131.1@6331.18,3978.41 6348.43,3961.16 6348.43,3941.38 v1(6361.81,3928)
AR_NERR_OUT: R21.1 RA6.5 U2.U15 | length 986.8
  Top Layer w5.5: v1(4276.95,4299.09) U2.U15@4292.7,4314.84
  Sig2 w4.2: v1(4276.95,4299.09) 4276.95,4297.07 4261.65,4281.77 4261.65,4261.26 4294.61,4228.3 4384.8,4228.3 4386.16,4226.94 4400.1,4226.94 4410.67,4216.36 4543.38,4216.36 4630.37,4303.36 4630.37,4342.88 4650.4,4362.91 4720.32,4362.91 4740.84,4342.39 4928.39,4342.39 v1(4972,4386)
  Bottom Layer w5.5: v1(4276.95,4299.09) 4288.62,4310.76 R21.1@4308.45,4310.76 ; RA6.5@4951.92,4351.02 4954.28,4351.02 4972,4368.74 v1(4972,4386)
AR_NERRIN: R22.1 RA6.6 U2.U14 | length 934.7
  Top Layer w5.5: U2.U14@4292.7,4283.34 v1(4308.45,4267.59)
  Sig2 w4.2: v1(4308.45,4267.59) 4339.34,4236.7 4388.27,4236.7 4389.64,4235.34 4406.08,4235.34 4416.65,4224.76 4539.9,4224.76 4618.27,4303.13 4618.27,4351.36 4663.61,4396.71 4734.22,4396.71 4741.63,4404.11 4975.53,4404.11 4994.69,4384.94 v1(4994.69,4362.02)
  Bottom Layer w5.5: v1(4308.45,4267.59) R22.1@4308.45,4288.76 ; RA6.6@4951.92,4335.27 4967.94,4335.27 v1(4994.69,4362.02)
AR_NRST: C130.1 R59.1 R108.1 TP14.1 U2.U11 U16.4 | length 1043.8
  Top Layer w5.5: v1(4276.95,4204.6) U2.U11@4292.7,4188.85 ; U16.4@4877.15,4175.21 4877.15,4200.15 4893.1,4216.1 v1(4904.16,4216.1) 4912.98,4207.29 R108.1@4912.98,4194
  Sig2 w4.2: v1(4276.95,4204.6) 4292.25,4219.9 4381.32,4219.9 4382.68,4218.54 4396.62,4218.54 4407.19,4207.96 4546.86,4207.96 4557.16,4218.26 4714.15,4218.26 4727.82,4231.92 4727.82,4269.26 4755.64,4297.09 4848.56,4297.09 4871.87,4273.78 4871.87,4226.53 4882.3,4216.1 v1(4904.16,4216.1)
  Bottom Layer w5.5: v1(4276.95,4204.6) 4289.15,4216.8 4289.15,4224.04 4286.81,4226.38 4263.32,4226.38 C130.1@4261.7,4228 4261.3,4228.4 4261.3,4307.3 4291.1,4337.1 TP14.1@4294.6,4337.1
AR_NRST_1: R177.2 R190.2 RA9.8 U16.1 | length 1927.3
  Top Layer w5.5: U16.1@4849.59,4143.71 R177.2@4849.59,4110.46 4849.59,4109.17 4844.26,4103.83 4842.18,4103.83 4835.84,4097.5 4835.84,4081.36 4866.7,4050.5 4978.96,4050.5 4996.29,4067.82 5142.29,4067.82 v1(5167.01,4092.54)
  Sig2 w4.2: v1(5167.01,4092.54) 5184.33,4075.22 5272.93,4075.22 5332.65,4015.5 5332.65,4007.74 5370.47,3969.91 5370.47,3917.48 5378.87,3909.08 5378.87,3840.32 5415.8,3803.39 5667.27,3803.39 5681.45,3817.57 5805.09,3817.57 5827.75,3794.91 5901.32,3794.91 5919.84,3813.43 6001.58,3813.43 6022.63,3792.38 v1(6107.15,3792.38)
  Bottom Layer w4.2: v1(6107.15,3792.38) 6108.34,3791.19 R190.2@6108.34,3764.53
  Bottom Layer w5.5: RA9.8@4960.68,3956.14 4961.37,3956.83 4971.09,3956.83 4978.25,3964 5056.12,3964 5087.12,3995 5087.12,4031.4 5102.47,4046.74 5150.4,4046.74 5167.01,4063.36 v1(5167.01,4092.54)
AR_NRST_2: C120.1 R124.1 SW2.1 U16.6 | length 387.8
  Top Layer w5.5: U16.6@4849.59,4175.21 4849.59,4183.68 4819.62,4213.65 4819.62,4271.16 4804.95,4285.83 4804.95,4390.94 4784.37,4411.52 C120.1@4784.37,4427.45 4806.96,4427.45 4816.38,4436.87 SW2.1@4854.16,4436.87 R124.1@4854.16,4471.7
AR_OSC_CLKOUT: RA1.2 TP17.1 U2.A14 | length 1259.9
  Top Layer w5.5: TP17.1@3701,4237 3706.66,4237 3734.51,4264.85 3770.28,4264.85 U2.A14@3788.76,4283.34 v1(3804.51,4267.59) ; v1(4696.57,4534.14) 4721.4,4534.14 4739.62,4515.92 4739.62,4491.75 RA1.2@4741.05,4490.32
  Sig2 w4.2: v1(3804.51,4267.59) 3804.51,4266.96 3812.31,4259.17 3812.31,4257.78 3820.71,4249.38 3820.71,4229.76 3829.67,4220.8 3842.35,4220.8 3855.34,4233.79 4131.25,4233.79 4244.25,4346.78 4346.9,4346.78 4369.1,4368.98 4384.04,4368.98 4426.37,4411.31 4534.4,4411.31 4646.7,4523.62 4686.05,4523.62 v1(4696.57,4534.14)
AR_PMIC_CLKOUT_SOP2: R85.1 R103.1 RA1.4 U2.V10 | length 997.6
  Top Layer w5.5: U2.V10@4324.2,4157.36 v1(4339.94,4173.11) ; v1(4690.56,4494.86) 4695.1,4490.32 RA1.4@4709.55,4490.32
  Sig2 w4.2: v1(4339.94,4173.11) 4337.92,4173.11 4321.73,4189.3 4266.87,4189.3 4261,4195.17 4261,4216.23 4230.16,4247.07 4230.16,4273.93 4240.02,4283.79 4251.79,4283.79 4261.2,4293.2 4261.2,4304.98 4271.44,4315.22 4384.1,4315.22 4418.24,4281.08 4418.24,4258.82 4427.09,4249.96 4529.46,4249.96 4587.77,4308.27 4587.77,4370.05 4650.65,4432.93 4650.65,4468.54 4646.07,4473.13 4646.07,4487.37 4653.46,4494.76 4686.25,4494.76 4686.34,4494.86 v1(4690.56,4494.86)
  Bottom Layer w5.5: v1(4339.94,4173.11) 4344.93,4178.09 R85.1@4344.93,4224.99 4344.93,4244.41 R103.1@4345.62,4245.1
AR_QSPI_CLK: R47.1 U2.H2 | length 650.4
  Top Layer w5.5: v1(3993.49,3921.14) U2.H2@4009.24,3905.39
  Sig2 w4.2: v1(3773.02,4015.63) 3662.13,4015.63 3654.68,4008.18 3654.68,3999.45 3663.21,3990.92 3706.39,3990.92 3737.31,3960 3771.94,3960 3793.6,3981.66 3817.72,3981.66 3843.6,3955.77 3869.39,3955.77 3891.32,3977.7 3989.07,3977.7 4008.79,3957.98 4008.79,3936.82 4008.98,3936.63 v1(3993.49,3921.14)
  Bottom Layer w5.5: R47.1@3734.37,4033.51 3755.94,4033.51 v1@3774.12,4015.33
AR_QSPI_CLK_T: R47.2 U9.6 | length 102.2
  Bottom Layer w5.5: R47.2@3734.37,4011.47 3747.4,4011.47 3757.25,4001.62 3757.25,3950.78 3750.99,3944.52 U9.6@3735.4,3944.52
AR_QSPI_CS: R43.1 U2.J2 U9.1 | length 772.5
  Top Layer w5.5: v1(4024.98,3921.14) U2.J2@4040.73,3905.39
  Sig1 w4.2: v1(3620.18,3859.13) 3620.18,3904.97 3625.01,3909.8 3630.38,3909.8 3639.85,3900.33 3647.3,3900.33 3652.12,3905.14 3652.12,3911.99 3639.73,3924.37 3639.73,3929.34 3647.76,3937.38 3652.78,3942.4 3652.87,3942.4 3667.07,3942.4 3678.43,3942.4 3681.27,3939.56 3681.27,3900.87 3684.11,3898.03 3692.63,3898.03 3695.47,3900.87 3695.47,3939.56 3698.31,3942.4 3706.83,3942.4 3709.67,3939.56 3709.67,3905.77 3712.51,3902.93 3721.03,3902.93 3723.87,3905.77 3723.87,3939.56 3726.71,3942.4 3730.97,3942.4 3735.14,3942.4 3771.98,3905.56 3969.83,3905.56 3976.59,3912.32 3976.59,3926.37 3985.96,3935.74 4010.38,3935.74 v1(4024.98,3921.14)
  Bottom Layer w5.5: v1(3620.18,3859.13) R43.1@3620.18,3875.43 3625.17,3880.41 U9.1@3625.17,3905.15
AR_QSPI_D0: R6.1 U2.H3 | length 707.4
  Top Layer w5.5: v1(3993.49,3952.63) U2.H3@4009.24,3936.89
  Sig2 w4.2: v1(3592.02,3967.77) 3592.02,4017.53 3600.13,4025.64 3615.59,4025.64 3635.24,4005.99 3635.24,3969.77 3656.25,3948.76 3776.34,3948.76 3799.43,3971.85 3814.73,3971.85 3839.99,3946.58 3872.3,3946.58 3894.55,3968.83 3977.29,3968.83 v1(3993.49,3952.63)
  Bottom Layer w5.5: v1(3592.02,3967.77) 3633.25,4009 3656,4009 3680.51,4033.51 R6.1@3706.27,4033.51
AR_QSPI_D0_T: R6.2 U9.5 | length 62.4
  Bottom Layer w5.5: R6.2@3706.27,4011.47 3706.27,3999.75 3720.96,3985.06 3720.96,3973.39 3730.15,3964.2 U9.5@3735.4,3964.2
AR_QSPI_D1: R46.1 U2.G2 | length 721.8
  Top Layer w5.5: v1(3961.99,3921.14) U2.G2@3977.74,3905.39
  Sig1 w4.2: v1(3576.23,3891.02) 3592,3906.8 3592,3933.42 3610.05,3951.47 3610.05,4005.15 3624.12,4019.22 3630.16,4019.22 3635,4014.38 3635,3994.04 3639.84,3989.2 3654.36,3989.2 3659.2,3994.04 3659.2,4019.22 3659.2,4021.32 3664.04,4026.16 3678.56,4026.16 3683.4,4021.32 3683.4,4019.22 3683.4,3994.04 3688.24,3989.2 3702.76,3989.2 3707.6,3994.04 3707.6,4014.38 3712.44,4019.22 3719.7,4019.22 3747.78,4019.22 3757.72,4009.29 3757.72,3944.96 3765.75,3936.93 3946.2,3936.93 v1(3961.99,3921.14)
  Bottom Layer w5.5: v1(3576.23,3891.02) 3583.61,3891.02 R46.1@3595.37,3902.79
AR_QSPI_D1_T: R46.2 U9.2 | length 29.8
  Bottom Layer w5.5: R46.2@3595.37,3924.83 U9.2@3625.17,3924.83
AR_QSPI_D2: R44.1 R48.1 U2.J3 | length 586.3
  Top Layer w5.5: v1(4024.98,3952.63) U2.J3@4040.73,3936.89
  Sig2 w4.2: v1@3581.24,4059.59 3755.83,4059.59 3788.32,4027.1 3788.32,4010.18 3799.77,3998.73 3812.87,3998.73 3837.05,3974.54 3876.28,3974.54 3887.84,3986.1 3993.54,3986.1 4017.19,3962.45 4017.19,3960.43 v1(4024.98,3952.63)
  Bottom Layer w5.5: v1@3581.24,4059.85 R44.1@3608.37,4059.85 ; R48.1@3608.37,4032.12 R44.1@3608.37,4059.85 ; R44.1@3608.85,4059.85 R44.1@3608.37,4059.85
  other v1: 3581.24,4060.3
AR_QSPI_D2_T: R48.2 U9.3 | length 140
  Bottom Layer w5.5: R48.2@3608.37,4010.07 3580.6,4010.07 3572,4001.47 3572,3961.71 3589.2,3944.52 U9.3@3625.17,3944.52
AR_QSPI_D3: R45.1 R49.1 U2.K2 | length 775.9
  Top Layer w5.5: v1(4056.48,3921.14) U2.K2@4072.23,3905.39
  Sig2 w4.2: v1(3836.01,4078.62) 3798.6,4078.62 3788.37,4088.84 3788.37,4142.05 3803.23,4156.91 3843.24,4156.91 3851.54,4148.61 3851.54,4069 3872.83,4047.7 4022.42,4047.7 4040.28,4029.84 4040.28,3937.33 v1(4056.48,3921.14)
  Bottom Layer w5.5: R49.1@3771.3,3958.79 3783.11,3970.6 3790.39,3970.6 R45.1@3798.7,3978.91 3798.7,3993.8 3803.85,3998.95 3819.33,3998.95 3855.08,4034.7 3855.08,4059.54 v1(3836.01,4078.62)
AR_QSPI_D3_T: R49.2 U9.7 | length 40.8
  Bottom Layer w5.5: U9.7@3735.4,3924.83 3759.4,3924.83 R49.2@3771.3,3936.74
AR_RS232RX: R5.2 U2.V16 U18.6 | length 970.5
  Top Layer w5.5: v1(3617.36,4202.17) 3617.36,4221.01 3626.27,4229.91 U18.6@3626.27,4303.01 ; U2.V16@4324.2,4346.33 v1(4339.94,4362.08) 4341.11,4363.24 R5.2@4378.13,4363.24
  Sig1 w4.2: v1(3617.36,4202.17) 3617.36,4220.36 3711.52,4314.52 3822,4314.52 3845.35,4337.86 4256.84,4337.86 4263.51,4331.19 4309.05,4331.19 v1(4339.94,4362.08)
AR_RS232RX_BT: R102.1 U15.4 | length 1331.3
  Sig2 w4.2: v1(5570.85,3978.06) 5551.62,3978.06 5520.67,4009.01 5520.67,4407.47 5535.31,4422.1 5731.3,4422.1 5817.87,4335.53 6153.89,4335.53 6176.16,4313.26 v1(6176.16,4311.82)
  Bottom Layer w5.5: U15.4@5519.85,3982 5534.46,3982 5538.4,3978.06 v1(5570.85,3978.06) ; v1(6176.16,4311.82) 6191.47,4311.82 6230.84,4272.45 R102.1@6268.98,4272.45
AR_RS232TX: R4.2 U2.U16 U18.10 | length 865.5
  Top Layer w5.5: v1@3686.89,4429.01 R4.2@3706.52,4429.01 3706.7,4428.83 3706.7,4337.35 3698.93,4329.59 U18.10@3691.23,4329.59 ; U2.U16@4292.7,4346.33 v1(4308.45,4362.08)
  Sig1 w4.2: v1@3686.89,4429.01 3670.11,4412.23 3670.11,4382.83 3706.68,4346.26 4292.63,4346.26 v1(4308.45,4362.08)
  other v1: 3686.89,4427.51
AR_RS232TX_BT: R90.1 U15.2 | length 1220.1
  Sig2 w4.2: v1(5550.13,4031.69) 5550.13,4060.05 5530.68,4079.51 5530.68,4395.41 5548.59,4413.32 5690.95,4413.32 5792.45,4311.82 v1(6146.94,4311.82)
  Bottom Layer w5.5: U15.2@5519.85,4021.37 5539.82,4021.37 v1(5550.13,4031.69) ; v1(6146.94,4311.82) 6164.69,4294.07 6183.21,4294.07 6228.29,4249 R90.1@6268.98,4249
AR_SCL: J3.2 R8.1 R32.1 R51.1 R62.2 R67.1 R70.2 R99.2 R187.2 RA2.4 | length 6077.4
  Top Layer w5.5: R32.1@3094.52,4276.93 3095.6,4278.01 3095.6,4293.02 v1(3096.68,4294.1) ; v1(4556.94,4458.91) 4556.98,4458.87 RA2.4@4556.98,4434.82
  Sig1 w4.2: v1(5446.44,3846.98) 5446.44,3852.98 5437.15,3862.28 5396.03,3862.28 5347.82,3910.48 5329.88,3910.48 5287.81,3868.41 5249.14,3868.41 5152.88,3772.15 5152.88,3742.72 5190.6,3705 5435.94,3705 5461.12,3679.81 5700.34,3679.81 5777.69,3757.16 5982.6,3757.16 5993.97,3768.53 6110.05,3768.53 6160.45,3818.93 6160.45,3855.33 v1(6160.81,3855.7)
  Sig1 w5.5: v1(3096.68,4294.1) 3096.68,4240.54 3113.15,4224.06 3159.4,4224.06 3190.57,4192.9 3518.31,4192.9 3543.58,4167.63 v1(3593.52,4167.63)
  Sig2 w4.2: v1(3872.5,3992.13) 3883.84,4003.46 3883.84,4022.21 3842.03,4064.02 3785.7,4064.02 3750.69,4099.03 3750.69,4129.02 3693.22,4186.49 3612.37,4186.49 v1(3593.52,4167.63) 3583.26,4177.89 3583.26,4191.15 3618.46,4226.35 3755.93,4226.35 3789.21,4259.64 3789.21,4277.61 3795.39,4283.79 3809.95,4283.79 3820.71,4273.04 3820.71,4261.26 3830.57,4251.4 3858.12,4251.4 3867.33,4242.19 4125.91,4242.19 4187,4303.28 4187,4329.49 4234.9,4377.38 4380.56,4377.38 4423.61,4420.43 4531.64,4420.43 4556.94,4445.73 v1(4556.94,4458.91) 4572.24,4474.21 4572.24,4516.44 4674.77,4618.97 5008.1,4618.97 5040.29,4586.79 J3.2@5040.29,4581.75 5138.87,4483.17 5138.87,4233.04 5349.45,4022.46 5349.45,4014.69 5387.27,3976.87 5387.27,3924.44 5395.67,3916.04 5395.67,3847.28 5411.27,3831.68 5431.14,3831.68 v1(5446.44,3846.98)
  Bottom Layer w4.2: v1@5446.62,3847.16 5446.62,3877.51 R70.2@5446.8,3877.69 ; v1@5446.8,3846.28 5471.24,3846.28 5490.54,3865.58 5490.54,3928.91 R67.1@5500.54,3938.91
  Bottom Layer w5.5: R8.1@3867.48,3958.98 3868.12,3959.62 3875.5,3959.62 3888.74,3972.86 R62.2@3888.74,3973.85 3884.7,3977.89 3884.7,3979.93 v1(3872.5,3992.13) ; J3.2@5040.29,4581.75 5094.81,4527.23 5102.77,4527.23 5146.22,4483.78 ; R99.2@5213.29,4485 5203.14,4495.15 5157.59,4495.15 5146.22,4483.78 ; R51.1@5232,4254.59 5146.22,4340.37 5146.22,4483.78 ; R187.2@6108.34,3892.26 6132.58,3892.26 6160.81,3864.03 v1(6160.81,3855.7)
AR_SDA: J3.3 R7.1 R28.1 R57.1 R61.2 R68.1 R71.2 R101.2 R186.2 RA2.3 | length 6264.1
  Top Layer w4.2: v1(3041.28,4292.69) 3041.28,4291.65 3061.8,4271.14 R28.1@3062.78,4271.14
  Top Layer w5.5: v1(4556.94,4486) 4557,4486 4574.69,4468.31 4574.69,4451.56 4572.73,4449.6 RA2.3@4572.73,4434.82
  Sig1 w4.2: v1(5417.61,3846.98) 5440.82,3823.76 5440.82,3815.62 5534.63,3721.81 5682.94,3721.81 5763.92,3802.79 5851.63,3802.79 6051.58,4002.74 6094.23,4002.74 6109.21,4017.72 6125.8,4017.72 6138.69,4004.84 v1(6138.69,3980.3)
  Sig1 w5.5: v1(3041.28,4292.69) 3070.62,4263.36 3070.62,4234.24 3096.06,4208.8 3138.32,4208.8 3167.05,4180.06 3392.68,4180.06 3408.92,4163.83 3530.47,4163.83 3551.73,4142.56 v1(3590.77,4142.56)
  Sig2 w4.2: v1(3867.5,4015.63) 3852.9,4030.23 3800.76,4030.23 3758.01,4072.98 3704.73,4072.98 3672.7,4105.01 3672.7,4129.44 3637.86,4164.28 3619.66,4164.28 3600.59,4145.2 3593.41,4145.2 v1(3590.77,4142.56) 3565.02,4168.31 3565.02,4222.1 3577.67,4234.75 3752.45,4234.75 3780.81,4263.11 3780.81,4281.09 3780.94,4281.22 3780.94,4284.82 3788.31,4292.19 3813.43,4292.19 3821.83,4283.79 3852.84,4283.79 3886.04,4250.59 4119.93,4250.59 4178.39,4309.06 4178.39,4332.76 4230.16,4384.52 4230.16,4405.38 4234.55,4409.77 4347.13,4409.77 4361.3,4395.61 4382.28,4395.61 4415.74,4429.07 4527.1,4429.07 4541.64,4443.61 4541.64,4470.7 v1(4556.94,4486) 4556.94,4524.29 4660.22,4627.57 5044.47,4627.57 J3.3@5090.29,4581.75 5147.27,4524.77 5147.27,4236.52 5357.85,4025.94 5357.85,4018.17 5395.67,3980.35 5395.67,3927.92 5417.61,3905.98 v1(5417.61,3846.98)
  Bottom Layer w4.2: R71.2@5409.05,3801.26 5409.05,3838.42 v1(5417.61,3846.98) 5435.14,3829.44 5480.79,3829.44 5489.14,3837.79 5601.1,3837.79 5614.67,3851.36 R68.1@5614.67,3937.06 R68.1@5616.53,3938.91
  Bottom Layer w5.5: R7.1@3840.93,3982.58 3840.93,3983.88 3855.31,3998.25 3855.31,4003.43 v1(3867.5,4015.63) 3887.79,4015.63 3893.37,4010.04 3893.37,3996.84 R61.2@3893.67,3996.54 ; R57.1@5198,4160.59 5198,4243.19 5134.72,4306.46 5134.72,4461.02 5081.06,4514.68 4981.61,4514.68 4943.26,4553.03 4943.26,4590.68 4965.74,4613.16 5058.88,4613.16 J3.3@5090.29,4581.75 5141.38,4530.66 5210.15,4530.66 5213.85,4534.36 R101.2@5263.15,4534.36 ; R186.2@6108.34,3931.22 6108.34,3949.95 v1(6138.69,3980.3)
AR_SOP0: R83.2 R158.2 R159.1 R174.2 | length 105.5
  Bottom Layer w5.5: R159.1@4223.5,4089.12 4223.5,4089.91 4227.05,4093.46 4236,4093.46 4239.22,4096.68 R158.2@4239.22,4119.6 4241.84,4122.21 4266.49,4122.21 R174.2@4269.1,4124.82 4268.19,4125.73 4268.19,4154.39 R83.2@4267.28,4155.3
AR_SOP1: R84.2 R170.2 R171.1 | length 100.6
  Bottom Layer w5.5: R84.2@4130.41,3922.4 4130.41,3933.54 R170.2@4143.32,3946.46 4143.32,3958.65 4148.32,3963.64 4176.89,3963.64 R171.1@4193.42,3980.18
AR_SOP2: R85.2 R172.2 R176.2 | length 111
  Bottom Layer w5.5: R85.2@4365.96,4224.99 4396.89,4224.99 4408.3,4213.57 4408.3,4189.48 R176.2@4400.62,4181.8 4401.11,4181.32 R172.2@4401.11,4153.05
AR_SPICLK1: R75.2 R136.2 U2.D2 | length 3950.4
  Top Layer w5.5: U2.D2@3883.25,3905.39 v1(3899,3889.64) ; R136.2@6759.84,4241 6759.84,4230.98 6763.81,4227 v1(6784.81,4227)
  Sig1 w4.2: v1(4524,3826) 4531.21,3818.79 4531.21,3793.53 4550.04,3774.7 4566.98,3774.7 4597.22,3744.46 4597.22,3688.79 4614.77,3671.24 4678.88,3671.24 4856.33,3671.23 4870.97,3685.87 4870.97,3757.93 4861.46,3767.45 4861.46,3807.71 4856.54,3812.62 4856.54,3843.69 4879.31,3866.46 4936.09,3866.46 4966.93,3897.3 5061.24,3897.3 5136.63,3821.91 5136.63,3743.44 5208.66,3671.41 5706.52,3671.41 5772.75,3737.64 5905.06,3737.64 5912.14,3730.56 6084.87,3730.56 6168.85,3814.53 6168.85,3824.51 6185.92,3841.59 6185.92,3880.56 6151.06,3915.42 6151.06,3942.98 6161.85,3953.76 6213.76,3953.76 6254,3994 6741,3994 6810.88,4063.88 6810.88,4200.93 v1(6784.81,4227)
  Sig2 w4.2: v1(3899,3889.64) 3922.46,3889.64 3952.12,3859.98 4035.89,3859.98 4049.24,3873.34 4346.39,3873.34 4361.54,3858.19 4494.81,3858.19 v1@4523,3830
  Bottom Layer w5.5: R75.2@3869.6,3892.2 3870.88,3890.92 3897.72,3890.92 v1(3899,3889.64)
